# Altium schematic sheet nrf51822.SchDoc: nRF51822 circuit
size A4; Revision: 2.0.0; SheetNumber: 1; SheetTotal: 3; DrawnBy: RUBR; ProjectNumber: 4393; PCBRevision: 0100RUBR; DocumentSize: A4; PCAName: PCA10000; PCBNumber: 400003
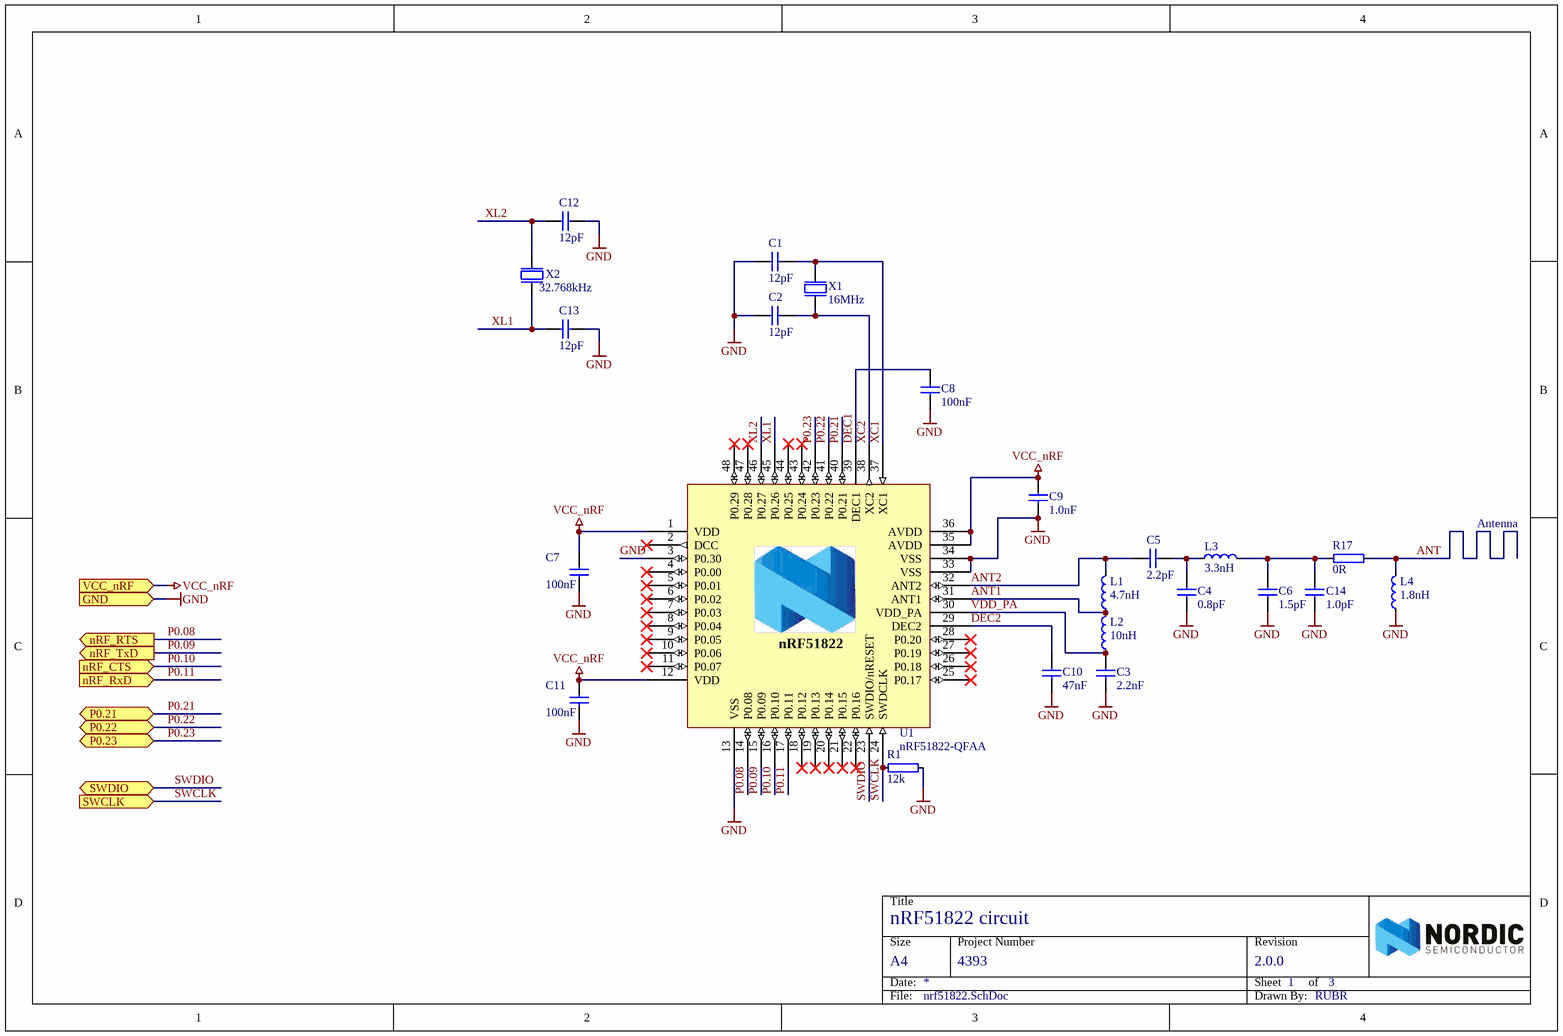
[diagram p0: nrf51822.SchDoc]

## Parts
C1  12pF  [CAPC1005X04L]
C2  12pF  [CAPC1005X04L]
C3  2.2nF  [CAPC1005X04L]
C4  0.8pF  [CAPC1005X04L]
C5  2.2pF  [CAPC1005X04L]
C6  1.5pF  [CAPC1005X04L]
C7  100nF  [CAPC1005X04L]
C8  100nF  [CAPC1005X04L]
C9  1.0nF  [CAPC1005X04L]
C10  47nF  [CAPC1005X04L]
C11  100nF  [CAPC1005X04L]
C12  12pF  [CAPC1005X04L]
C13  12pF  [CAPC1005X04L]
C14  1.0pF  [CAPC1005X04L]
L1  4.7nH  [INDC1005X04L]
L2  10nH  [INDC1005X04L]
L3  3.3nH  [INDC1005X04L]
L4  1.8nH  [INDC1005X04L]
R1  12k  [RESC1005X04L]
R17  0R  [RESC1005X04L]
U1  nRF51822-QFAA  [QFN40P600X600X90-48N]
X1  16MHz  [BT-XTAL_2520]
X2  32.768kHz  [FC-135]

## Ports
GND (in), nRF_CTS (in), nRF_RTS (out), nRF_RxD (in), nRF_TxD (out), P0.21 (bidir), P0.22 (bidir), P0.23 (bidir), SWCLK (in), SWDIO (bidir), VCC_nRF (in)

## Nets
GND: C1.2 C2.2 C3.2 C4.2 C6.2 C7.2 C8.2 C9.2 C10.2 C11.2 C12.2 C13.2 C14.2 L4.1 R1.2 U1.3(P0.30) U1.13(VSS) U1.33(VSS) U1.34(VSS) U1.49 X1.2(GND) X1.4(GND) ; port GND
VCC_nRF: C7.1 C9.1 C11.1 U1.1(VDD) U1.12(VDD) U1.35(AVDD) U1.36(AVDD) ; port VCC_nRF
ANT: L4.2 R17.2
ANT1: L1.1 L2.2 U1.31(ANT1)
ANT2: C5.1 L1.2 U1.32(ANT2)
DEC1: C8.1 U1.39(DEC1)
DEC2: C10.1 U1.29(DEC2)
P0.08: U1.14(P0.08) ; port nRF_RTS
P0.09: U1.15(P0.09) ; port nRF_TxD
P0.10: U1.16(P0.10) ; port nRF_CTS
P0.11: U1.17(P0.11) ; port nRF_RxD
P0.21: U1.40(P0.21) ; port P0.21
P0.22: U1.41(P0.22) ; port P0.22
P0.23: U1.42(P0.23) ; port P0.23
SWCLK: R1.1 U1.24(SWDCLK) ; port SWCLK
SWDIO: U1.23(SWDIO/nRESET) ; port SWDIO
VDD_PA: C3.1 L2.1 U1.30(VDD_PA)
XC1: C1.1 U1.37(XC1) X1.1(inp)
XC2: C2.1 U1.38(XC2) X1.3(out)
XL1: C13.1 U1.45(P0.26) X2.2(out)
XL2: C12.1 U1.46(P0.27) X2.1(inp)
NetC4_1: C4.1 C5.2 L3.1
NetC6_1: C6.1 C14.1 L3.2 R17.1

Not connected (* = marked no-connect by the designer): U1 2(DCC)* 4(P0.00)* 5(P0.01)* 6(P0.02)* 7(P0.03)* 8(P0.04)* 9(P0.05)* 10(P0.06)* 11(P0.07)* 18(P0.12)* 19(P0.13)* 20(P0.14)* 21(P0.15)* 22(P0.16)* 25(P0.17)* 26(P0.18)* 27(P0.19)* 28(P0.20)* 43(P0.24)* 44(P0.25)* 47(P0.28)* 48(P0.29)*

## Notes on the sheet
- Antenna

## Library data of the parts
C1 C2 C12 C13 = C0402-12p: Capacitor, NP0, ±2%; Note: 50V; Artikkelnr Noca: 20029159
C3 = C0402-2n2: Capacitor, X7R, ±10%; Note: 50V; Artikkelnr Noca: 20039221
C4 = C0402-0.8p: Capacitor, NP0, ±5%; Note: 50V; Artikkelnr Noca: 20029147
C5 = C0402-2.2p: Capacitor, NP0, ±0.1pF; Note: 50V; Artikkelnr Noca: 20029145
C6 = C0402-1.5p: Capacitor, NP0, ±0.1pF; Note: 50V; Artikkelnr Noca: 20029139
C7 C8 C11 = C0402-100n: Capacitor, X7R, ±10%; Note: 16V; Artikkelnr Noca: 20039200
C9 = C0402-1n0: Capacitor, X7R, ±10%; Note: 50V; Artikkelnr Noca: 20039223
C10 = C0402-47n: Capacitor, X7R, ±10%; Note: Chip Cap 10%; Artikkelnr Noca: 20039389
C14 = C0402-1.0p: Capacitor, NP0, ±0.1pF; Note: 50V; Artikkelnr Noca: 20029140
L1 = L0402-4n7: Inductor, 160mA, ±0.1nH; Manufacturer: Murata; Manufacturer Part Number: LQP15MN4N7B02D; Note: High frequency chip inductor ±5%; Artikkelnr Noca: 33029164
L2 = L0402-10n: Inductor, 100mA, ±2%; Manufacturer: Murata; Manufacturer Part Number: LQP15MN10NG02D; Note: High frequency chip inductor ±5%; Artikkelnr Noca: 33029425
L3 = L0402-3n3: Inductor, 190mA, ±0.1nH; Manufacturer: Murata; Manufacturer Part Number: LQP15MN3N3B02D; Note: High frequency chip inductor ±5%; Artikkelnr Noca: 33029369
L4 = L0402-1n8: Inductor, 280mA, ±0.1nH; Manufacturer: Murata; Manufacturer Part Number: LQP15MN1N8B02D; Note: High frequency chip inductor ±5%; Artikkelnr Noca: 33029171
R1 = R0402-12k: Resistor, ±1%, 0.063W; Note: Chip Res 1%; Artikkelnr Noca: 27049099
R17 = R0402-0R: Resistor, ±5%, 0.063W; Note: Chip Res 5%; Artikkelnr Noca: 27049000
U1 = nRF51822-Q48-6x6_DCDC: Multi-protocol Bluetooth Low Energy and 2.4GHz proprietary system-on-chip; Manufacturer: Nordic Semiconductor; Note: nRF51822 - QFN48 6x6 0.4mm pitch; Artikkelnr Noca: 15079200
X1 = NX2520SA-16MHZ-STD-CSW-5: XTAL SMD 2520, 16MHz, 8pF, ±15ppm; Manufacturer: NDK; Note: XTAL SMD 16.000MHz; Artikkelnr Noca: 22019192
X2 = XTAL_FC-135 32.768k: EPSON TOYOCOM - FC-135 32.768KHZ ±20PPM,9.0PF - CRYSTAL, SM, WATCH; 2nd source part number: 127-8037; Note: XTAL SMD 32.768kHz, 3215; Artikkelnr Noca: 22019091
